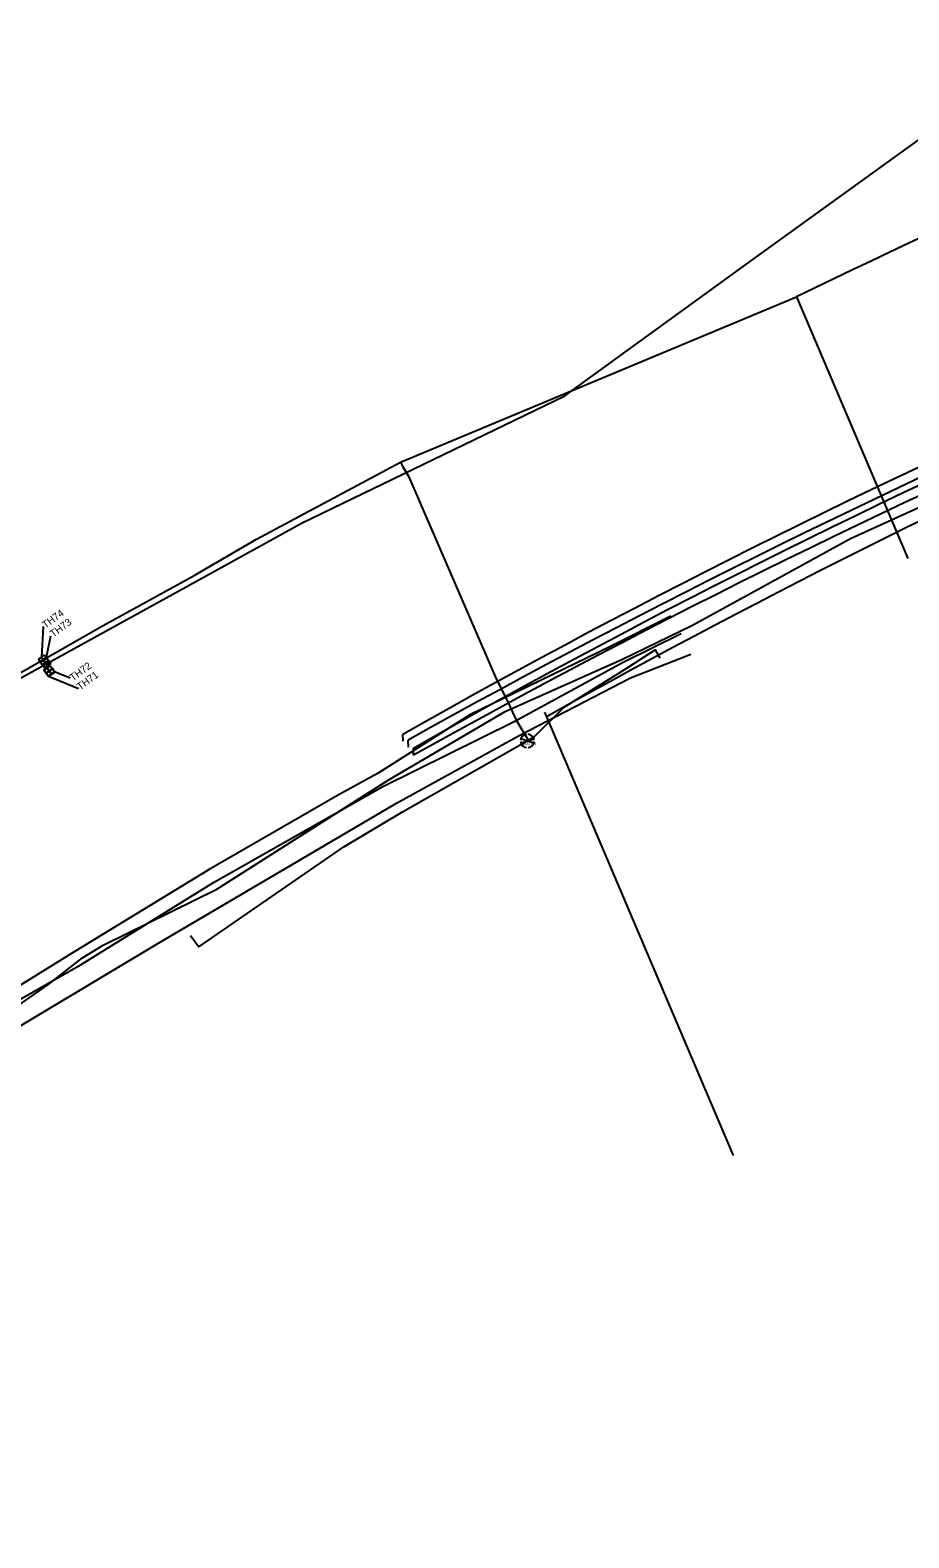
# Model space of a CAD drawing. Extents: x 507915 to 518914, y 880723 to 883087.
# Drawn here: x 509259.1 to 509548.5, y 882108.6 to 882605.4 of the extents above; entities that cross this region are included whole.
import ezdxf

# ---------------------------------------------------------------- set-up
doc = ezdxf.new("R2010")
doc.units = 0
for name, color, linetype in [('CGFace_ep', 7, 'Continuous'), ('ConduitDB', 7, 'Continuous'), ('ConduitOT', 7, 'Continuous'), ('ConstLines', 7, 'Continuous'), ('Driveway_ep', 7, 'Continuous'), ('GuardrailLt_ep', 7, 'Continuous'), ('GuardrailRt_ep', 7, 'Continuous'), ('Miscellaneous3', 7, 'Continuous'), ('PavtAsphalt_ep', 7, 'Continuous'), ('PMBikeLane_ep', 7, 'Continuous'), ('PoleLight', 7, 'Continuous'), ('PoleLight_ep', 7, 'Continuous'), ('SignSingle_ep', 7, 'Continuous')]:
    doc.layers.add(name, color=color, linetype=linetype)

msp = doc.modelspace()

# ---------------------------------------------------------------- linework, layer by layer
at = {"layer": 'CGFace_ep'}
msp.add_lwpolyline([(509435.21, 882484.91), (509498.35, 882530.75), (509568.03, 882581.03)], dxfattribs=at)
at = {"layer": 'ConduitDB'}
msp.add_line((509511.48, 882517.48), (509548.17, 882431.3), dxfattribs=at)
msp.add_arc((510737.04, 880000.16), 2799.81, 111.48627, 115.95925, dxfattribs=at)
at = {"layer": 'ConduitOT'}
for p, q in [((509490.75, 882234.58), (509428.56, 882380.66)), ((509381.91, 882371.06), (509381.85, 882373.36)), ((509383.69, 882369.16), (509383.63, 882371.45)), ((509385.37, 882366.45), (509385.31, 882368.75))]:
    msp.add_line(p, q, dxfattribs=at)
for centre, radius, start, end in [((510634.03, 880163.93), 2539.59, 106.97728, 119.54212), ((510665.52, 880080.42), 2625.28, 107.14845, 119.22809), ((510595.15, 880246.58), 2442.8, 106.68408, 119.68726), ((510646.43, 880115.18), 2580.4, 106.94094, 119.25537), ((510646.59, 880206.11), 2490.83, 107.67393, 119.2544)]:
    msp.add_arc(centre, radius, start, end, dxfattribs=at)
at = {"layer": 'ConstLines'}
for points in [[(509150.52, 882330.83), (509187.35, 882352.15), (509251.15, 882390.97), (509283.1, 882409.2), (509313.1, 882425.71), (509333.68, 882437.65), (509381.11, 882463), (509511.48, 882517.48)], [(509381.11, 882463), (509381.7, 882461.69), (509383.64, 882458.41), (509412.55, 882391.61), (509416.46, 882384.04), (509419.06, 882378.22), (509423.17, 882371.34), (509423.47, 882371.54), (509425.22, 882372.63), (509434.94, 882382.29), (509454.71, 882394.6), (509464.93, 882401.19), (509466.48, 882398.42)], [(509311.89, 882307.09), (509314.62, 882303.34), (509362.37, 882336.32), (509381.74, 882347.84), (509422.83, 882371.21), (509423.17, 882371.34)]]:
    msp.add_lwpolyline(points, dxfattribs=at)
at = {"layer": 'Driveway_ep'}
msp.add_lwpolyline([(509470.15, 882412.29), (509450.24, 882402.26), (509403.86, 882379.8), (509373.73, 882360.54), (509360.26, 882353.19), (509318.09, 882328.86), (509274.11, 882302.04), (509240.02, 882280.9), (509217.6, 882265.28), (509213.42, 882264.48), (509212.3, 882264.04), (509210.28, 882262.92), (509172.92, 882230.49), (509113.97, 882188.99), (509087.11, 882169.95), (509067.76, 882154.57), (509006.28, 882108.6)], dxfattribs=at)
at = {"layer": 'GuardrailRt_ep'}
for p, q in [((509263.39, 882408.86), (509262.81, 882398.79)), ((509265.74, 882405.7), (509264.4, 882398.73)), ((509274.97, 882388.39), (509265.13, 882392.43)), ((509272.28, 882391.9), (509267.11, 882393.99))]:
    msp.add_line(p, q, dxfattribs=at)
at = {"layer": 'Miscellaneous3'}
for points in [[(508882.11, 882139.28), (508990.02, 882214.29), (509029.72, 882243.96), (509087.02, 882285.78), (509130.99, 882317.86), (509136.55, 882321.71), (509138.14, 882323.57), (509145.35, 882327.1), (509198.61, 882360.32), (509243.19, 882384.95), (509308.25, 882420.73), (509348.67, 882443.03), (509435.21, 882484.91)], [(509130.88, 882181.71), (509131.05, 882184.29), (509136.67, 882194.39), (509176.07, 882223.49), (509242.19, 882269.15), (509301.71, 882304.81), (509379.73, 882350.73), (509420.13, 882372.96), (509456.8, 882391.95), (509476.67, 882399.78)], [(509130.88, 882181.71), (509131.05, 882184.29), (509136.67, 882194.39), (509176.07, 882223.49), (509204.83, 882245.76), (509242.19, 882269.15), (509301.71, 882304.81), (509379.73, 882350.73), (509420.13, 882372.96), (509456.8, 882391.95), (509476.67, 882399.78)]]:
    msp.add_lwpolyline(points, dxfattribs=at)
at = {"layer": 'PavtAsphalt_ep'}
msp.add_lwpolyline([(509213.58, 882113.61), (509213.91, 882115.53), (509214.71, 882140.61), (509214.38, 882191.99), (509210.5, 882232.36), (509212.63, 882254.27), (509212.52, 882255.04), (509222.59, 882267.57), (509239.56, 882276.92), (509275.89, 882297.56), (509319.52, 882324.51), (509375.22, 882356.19), (509418.49, 882377.58), (509454.45, 882397.18), (509473.5, 882406.55)], dxfattribs=at)
at = {"layer": 'PMBikeLane_ep'}
for p, q in [((509261.78, 882398.07), (509263.83, 882399.51)), ((509263.83, 882399.51), (509265.27, 882397.47)), ((509262.81, 882398.79), (509261.78, 882398.07)), ((509263.23, 882396.02), (509261.78, 882398.07)), ((509261.78, 882398.07), (509262.51, 882397.05)), ((509262.36, 882397.29), (509264.4, 882398.73)), ((509263.38, 882398.01), (509262.36, 882397.29)), ((509263.8, 882395.24), (509262.36, 882397.29)), ((509262.36, 882397.29), (509263.08, 882396.27)), ((509262.51, 882397.05), (509264.55, 882398.49)), ((509262.51, 882397.05), (509263.53, 882397.77)), ((509262.81, 882398.79), (509264.25, 882396.75)), ((509263.53, 882397.77), (509262.81, 882398.79)), ((509263.08, 882396.27), (509265.12, 882397.71)), ((509263.08, 882396.27), (509264.1, 882396.99)), ((509265.27, 882397.47), (509263.23, 882396.02)), ((509263.38, 882398.01), (509264.82, 882395.97)), ((509264.1, 882396.99), (509263.38, 882398.01)), ((509264.55, 882398.49), (509263.53, 882397.77)), ((509263.53, 882397.77), (509264.25, 882396.75)), ((509263.53, 882397.77), (509263.53, 882397.77)), ((509263.63, 882394.59), (509265.67, 882396.03)), ((509264.65, 882395.31), (509263.63, 882394.59)), ((509265.07, 882392.55), (509263.63, 882394.59)), ((509263.63, 882394.59), (509264.35, 882393.57)), ((509263.69, 882394.47), (509265.73, 882395.91)), ((509264.71, 882395.19), (509263.69, 882394.47)), ((509265.13, 882392.43), (509263.69, 882394.47)), ((509263.69, 882394.47), (509264.41, 882393.45)), ((509265.84, 882396.69), (509263.8, 882395.24)), ((509265.12, 882397.71), (509264.1, 882396.99)), ((509264.1, 882396.99), (509264.82, 882395.97)), ((509264.1, 882396.99), (509264.1, 882396.99)), ((509264.25, 882396.75), (509265.27, 882397.47)), ((509264.35, 882393.57), (509266.39, 882395.01)), ((509264.4, 882398.73), (509265.84, 882396.69)), ((509264.41, 882393.45), (509266.45, 882394.89)), ((509265.27, 882397.47), (509264.55, 882398.49)), ((509264.65, 882395.31), (509266.09, 882393.27)), ((509265.37, 882394.29), (509264.65, 882395.31)), ((509264.71, 882395.19), (509266.15, 882393.15)), ((509265.43, 882394.17), (509264.71, 882395.19)), ((509264.82, 882395.97), (509265.84, 882396.69)), ((509265.84, 882396.69), (509265.12, 882397.71)), ((509266.39, 882395.01), (509265.37, 882394.29)), ((509266.45, 882394.89), (509265.43, 882394.17)), ((509265.67, 882396.03), (509267.11, 882393.99)), ((509265.73, 882395.91), (509267.17, 882393.87)), ((509267.11, 882393.99), (509266.39, 882395.01)), ((509267.17, 882393.87), (509266.45, 882394.89)), ((509264.35, 882393.57), (509265.37, 882394.29)), ((509264.41, 882393.45), (509265.43, 882394.17)), ((509267.11, 882393.99), (509265.07, 882392.55)), ((509267.17, 882393.87), (509265.13, 882392.43)), ((509265.37, 882394.29), (509266.09, 882393.27)), ((509265.37, 882394.29), (509265.37, 882394.29)), ((509265.43, 882394.17), (509266.15, 882393.15)), ((509265.43, 882394.17), (509265.43, 882394.17)), ((509266.09, 882393.27), (509267.11, 882393.99)), ((509266.15, 882393.15), (509267.17, 882393.87))]:
    msp.add_line(p, q, dxfattribs=at)
at = {"layer": 'PoleLight'}
msp.add_lwpolyline([(509477.23, 882409.32), (509529.31, 882437.92), (509668.96, 882501.53), (509673.26, 882492.1), (509701.26, 882505)], dxfattribs=at)
at = {"layer": 'PoleLight_ep'}
msp.add_lwpolyline([(509066.19, 882157), (509063.7, 882160.81), (509096.65, 882182.65), (509173.39, 882230.11), (509240.49, 882273.93), (509264.92, 882290.87), (509276.3, 882299.74), (509283.12, 882303.89), (509320.52, 882322.39), (509376.96, 882358.25), (509415.58, 882380.91), (509454.19, 882398.17), (509477.23, 882409.32)], dxfattribs=at)
at = {"layer": 'SignSingle_ep'}
for p, q in [((509420.69, 882370.5), (509424.96, 882371.92)), ((509424.96, 882370.5), (509420.69, 882371.92)), ((509422.83, 882371.21), (509422.83, 882371.21))]:
    msp.add_line(p, q, dxfattribs=at)
for start, end in [(96.3794, 173.6206), (186.3794, 263.6206), (6.3794, 83.6206), (276.3794, 353.6206)]:
    msp.add_arc((509422.83, 882371.21), 2.25, start, end, dxfattribs=at)

# ---------------------------------------------------------------- texts
at = {"layer": 'GuardrailLt_ep'}
for s, p in [('TH74', (509264.12, 882408.13)), ('TH73', (509266.68, 882405.18)), ('TH72', (509273.18, 882390.76)), ('TH71', (509275.56, 882387.78))]:
    msp.add_text(s, height=2.4, rotation=36.4175, dxfattribs=at).set_placement(p)
at = {"layer": 'SignSingle_ep'}
msp.add_text('WATER', height=0.9, dxfattribs=at).set_placement((509421.28, 882369.78))

doc.saveas('drawing.dxf')
